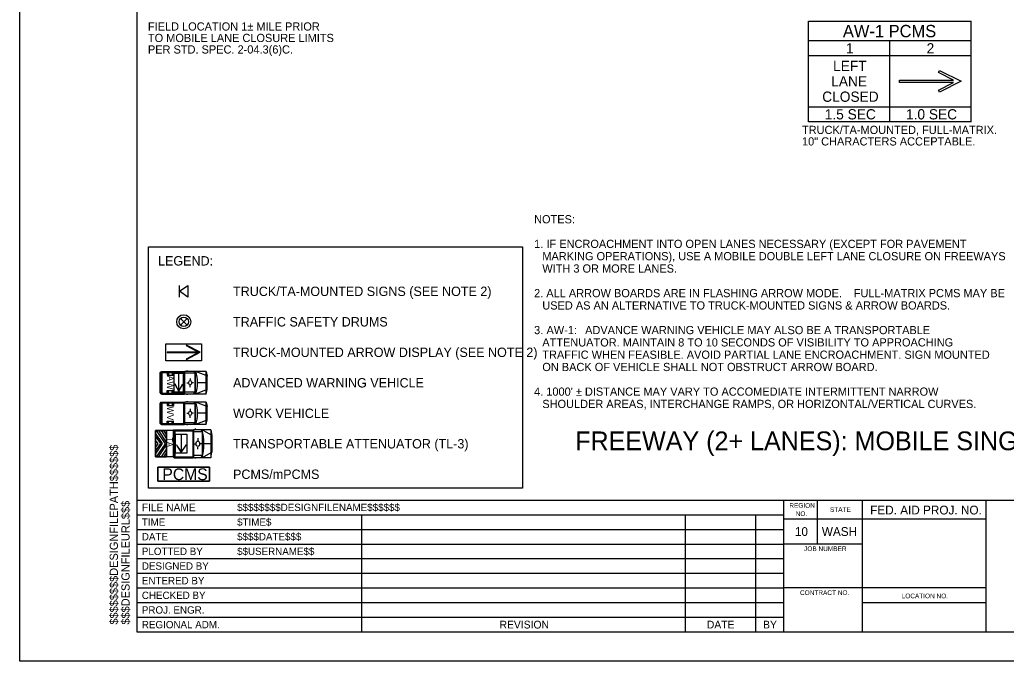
# Model space of a CAD drawing. Extents: x 0 to 17, y 0 to 11.
# Drawn here: x 0 to 8.42, y 0 to 5.47 of the extents above; entities that cross this region are included whole.
import ezdxf

# ---------------------------------------------------------------- set-up
doc = ezdxf.new("R2010")
doc.units = 0
for name, color, linetype in [('SH_GI_PlotLimits', 7, 'Continuous'), ('SH_GI_SheetBorder1', 7, 'Continuous'), ('SH_GI_SheetBorder2', 7, 'Continuous'), ('SH_GI_SheetBorder3', 7, 'Continuous'), ('SH_GI_SheetTextInCells', 7, 'Continuous'), ('SH_GI_TitleBlockText', 7, 'Continuous'), ('TR_WZ_PCMS', 7, 'Continuous'), ('TR_WZ_PortableChangeMessageSign', 7, 'Continuous'), ('TR_WZ_PortableSignMountBlk-Org', 7, 'Continuous'), ('TR_WZ_ProtectiveVehicle', 7, 'Continuous'), ('TR_WZ_TrafficSafetyDrum', 7, 'Continuous'), ('TR_WZ_TransportableAttenuator', 7, 'Continuous'), ('TR_WZ_WorkZoneTextCurrent', 7, 'Continuous')]:
    doc.layers.add(name, color=color, linetype=linetype)

msp = doc.modelspace()

# ---------------------------------------------------------------- linework, layer by layer
at = {"layer": 'SH_GI_PlotLimits'}
msp.add_lwpolyline([(0, 11), (17, 11), (17, 0), (0, 0)], close=True, dxfattribs=at)
at = {"layer": 'SH_GI_SheetBorder1'}
for p, q in [((8.245, 1.2125), (6.52, 1.2125)), ((1, 1.125), (2.92, 1.125)), ((2.92, 1.125), (6.52, 1.125)), ((1, 1), (2.92, 1)), ((2.92, 1), (6.52, 1)), ((1, 0.875), (2.92, 0.875)), ((2.92, 0.875), (6.52, 0.875)), ((1, 0.75), (2.92, 0.75)), ((2.92, 0.75), (6.52, 0.75)), ((1, 0.625), (2.92, 0.625)), ((2.92, 0.625), (6.52, 0.625)), ((1, 0.5), (2.92, 0.5)), ((2.92, 0.5), (6.52, 0.5)), ((7.1913, 0.5), (8.245, 0.5)), ((1, 0.375), (2.92, 0.375))]:
    msp.add_line(p, q, dxfattribs=at)
at = {"layer": 'SH_GI_SheetBorder2'}
for p, q in [((6.8073, 1), (6.8073, 1.375)), ((7.1913, 1), (6.52, 1)), ((8.245, 0.625), (6.52, 0.625)), ((2.92, 0.375), (6.52, 0.375))]:
    msp.add_line(p, q, dxfattribs=at)
at = {"layer": 'SH_GI_SheetBorder3'}
for p, q in [((1, 10.75), (1, 0.25)), ((1, 1.375), (16.75, 1.375)), ((6.52, 0.25), (6.52, 1.375)), ((7.1913, 0.25), (7.1913, 1.375)), ((8.245, 0.25), (8.245, 1.375)), ((1, 1.25), (6.52, 1.25)), ((2.92, 0.25), (2.92, 1.25)), ((5.68, 0.25), (5.68, 1.25)), ((6.28, 0.25), (6.28, 1.25)), ((1, 0.25), (16.75, 0.25))]:
    msp.add_line(p, q, dxfattribs=at)
at = {"layer": 'TR_WZ_PCMS'}
for points in [[(1.6191, 1.655), (1.6191, 1.535), (1.1791, 1.535), (1.1791, 1.655), (1.6191, 1.655)], [(1.1791, 1.655), (1.1791, 1.535), (1.6191, 1.535), (1.6191, 1.655), (1.1791, 1.655)]]:
    msp.add_lwpolyline(points, dxfattribs=at)
at = {"layer": 'TR_WZ_PortableChangeMessageSign'}
for p, q in [((6.7302, 5.4586), (8.1162, 5.4586)), ((6.7302, 4.6018), (6.7302, 5.4586)), ((8.1162, 4.6018), (8.1162, 5.4586)), ((8.1162, 5.2906), (6.7302, 5.2906)), ((7.4232, 4.6018), (7.4232, 5.2906)), ((7.4232, 5.1646), (6.7302, 5.1646)), ((8.1162, 5.1646), (7.4232, 5.1646)), ((7.8483, 5.0395), (8.0322, 4.9462)), ((7.5072, 4.9357), (7.5072, 4.9567)), ((7.5072, 4.9567), (7.9671, 4.9567)), ((7.9671, 4.9357), (7.5072, 4.9357)), ((6.7302, 4.7278), (7.4232, 4.7278)), ((7.4232, 4.7278), (8.1162, 4.7278)), ((8.1162, 4.6018), (6.7302, 4.6018))]:
    msp.add_line(p, q, dxfattribs=at)
for points in [[(7.9671, 4.9567), (7.8389, 5.0208), (7.8436, 5.0302), (7.8483, 5.0395)], [(8.0322, 4.9462), (7.8483, 4.8528), (7.8436, 4.8622), (7.8389, 4.8715), (7.9671, 4.9357)]]:
    msp.add_lwpolyline(points, dxfattribs=at)
at = {"layer": 'TR_WZ_PortableSignMountBlk-Org'}
msp.add_line((1.3631, 3.105), (1.3631, 3.205), dxfattribs=at)
msp.add_lwpolyline([(1.3631, 3.155), (1.435, 3.205), (1.435, 3.105)], close=True, dxfattribs=at)
at = {"layer": 'TR_WZ_ProtectiveVehicle'}
for p, q in [((1.1993, 2.288), (1.1993, 2.462)), ((1.2035, 2.4678), (1.2078, 2.4678)), ((1.2078, 2.2822), (1.2078, 2.4678)), ((1.2085, 2.471), (1.406, 2.471)), ((1.2085, 2.279), (1.2085, 2.471)), ((1.2141, 2.2867), (1.2141, 2.4633)), ((1.2141, 2.4633), (1.4004, 2.4633)), ((1.2586, 2.4633), (1.2586, 2.4413)), ((1.2586, 2.4413), (1.3114, 2.4413)), ((1.2692, 2.4633), (1.2692, 2.4413)), ((1.3018, 2.4633), (1.3018, 2.4413)), ((1.3114, 2.4633), (1.3114, 2.4413)), ((1.4004, 2.2867), (1.4004, 2.4633)), ((1.406, 2.279), (1.406, 2.471)), ((1.4086, 2.279), (1.4086, 2.471)), ((1.59, 2.471), (1.4086, 2.471)), ((1.4976, 2.4561), (1.4086, 2.4561)), ((1.4334, 2.4737), (1.4225, 2.4737)), ((1.4881, 2.4561), (1.4976, 2.471)), ((1.4976, 2.279), (1.4976, 2.471)), ((1.4993, 2.279), (1.4993, 2.471)), ((1.59, 2.4358), (1.4993, 2.471)), ((1.59, 2.279), (1.59, 2.471)), ((1.59, 2.471), (1.5989, 2.4322)), ((1.1993, 2.3885), (1.2078, 2.3849)), ((1.1993, 2.3615), (1.2078, 2.3651)), ((1.2016, 2.375), (1.2055, 2.375)), ((1.2035, 2.3723), (1.2035, 2.3777)), ((1.4245, 2.3757), (1.4388, 2.3754)), ((1.4406, 2.3753), (1.4406, 2.3753)), ((1.4535, 2.4119), (1.4537, 2.3975)), ((1.4831, 2.3749), (1.471, 2.3749)), ((1.59, 2.375), (1.5171, 2.375)), ((1.5989, 2.3178), (1.5989, 2.4322)), ((1.2035, 2.2822), (1.2078, 2.2822)), ((1.2085, 2.279), (1.406, 2.279)), ((1.2141, 2.2867), (1.4004, 2.2867)), ((1.2586, 2.3087), (1.3114, 2.3087)), ((1.2586, 2.2867), (1.2586, 2.3087)), ((1.2692, 2.2867), (1.2692, 2.3087)), ((1.3018, 2.2867), (1.3018, 2.3087)), ((1.3114, 2.2867), (1.3114, 2.3087)), ((1.4976, 2.2939), (1.4086, 2.2939)), ((1.59, 2.279), (1.4086, 2.279)), ((1.4334, 2.2763), (1.4225, 2.2763)), ((1.4541, 2.3369), (1.4541, 2.3525)), ((1.4976, 2.279), (1.4861, 2.2939)), ((1.59, 2.3142), (1.4993, 2.279)), ((1.59, 2.279), (1.5989, 2.3178)), ((1.1993, 2.028), (1.1993, 2.202)), ((1.2035, 2.2078), (1.2078, 2.2078)), ((1.2078, 2.0222), (1.2078, 2.2078)), ((1.2085, 2.211), (1.406, 2.211)), ((1.2085, 2.019), (1.2085, 2.211)), ((1.2141, 2.0267), (1.2141, 2.2033)), ((1.2141, 2.2033), (1.4004, 2.2033)), ((1.2586, 2.2033), (1.2586, 2.1813)), ((1.2692, 2.2033), (1.2692, 2.1813)), ((1.3018, 2.2033), (1.3018, 2.1813)), ((1.3114, 2.2033), (1.3114, 2.1813)), ((1.4004, 2.0267), (1.4004, 2.2033)), ((1.406, 2.019), (1.406, 2.211)), ((1.4086, 2.019), (1.4086, 2.211)), ((1.59, 2.211), (1.4086, 2.211)), ((1.4976, 2.1961), (1.4086, 2.1961)), ((1.4334, 2.2137), (1.4225, 2.2137)), ((1.4881, 2.1961), (1.4976, 2.211)), ((1.4976, 2.019), (1.4976, 2.211)), ((1.4993, 2.019), (1.4993, 2.211)), ((1.59, 2.1758), (1.4993, 2.211)), ((1.59, 2.019), (1.59, 2.211)), ((1.59, 2.211), (1.5989, 2.1722)), ((1.1993, 2.1285), (1.2078, 2.1249)), ((1.1993, 2.1015), (1.2078, 2.1051)), ((1.2016, 2.115), (1.2055, 2.115)), ((1.2035, 2.1123), (1.2035, 2.1177)), ((1.2586, 2.1813), (1.3114, 2.1813)), ((1.4245, 2.1157), (1.4388, 2.1154)), ((1.4406, 2.1153), (1.4406, 2.1153)), ((1.4535, 2.1519), (1.4537, 2.1375)), ((1.4831, 2.1149), (1.471, 2.1149)), ((1.59, 2.115), (1.5171, 2.115)), ((1.5989, 2.0578), (1.5989, 2.1722)), ((1.2035, 2.0222), (1.2078, 2.0222)), ((1.2141, 2.0267), (1.4004, 2.0267)), ((1.2586, 2.0487), (1.3114, 2.0487)), ((1.2586, 2.0267), (1.2586, 2.0487)), ((1.2692, 2.0267), (1.2692, 2.0487)), ((1.3018, 2.0267), (1.3018, 2.0487)), ((1.3114, 2.0267), (1.3114, 2.0487)), ((1.4976, 2.0339), (1.4086, 2.0339)), ((1.4541, 2.0769), (1.4541, 2.0925)), ((1.4976, 2.019), (1.4861, 2.0339)), ((1.59, 2.0542), (1.4993, 2.019)), ((1.59, 2.019), (1.5989, 2.0578)), ((1.2085, 2.019), (1.406, 2.019)), ((1.59, 2.019), (1.4086, 2.019)), ((1.4334, 2.0163), (1.4225, 2.0163))]:
    msp.add_line(p, q, dxfattribs=at)
for centre, major_axis, start_param, end_param in [((1.2035, 2.462), (0, 0.00586), 0, 1.570796), ((1.3697, 2.375), (0, 0.2015), 4.215667, 5.208926), ((1.2035, 2.288), (0, -0.00586), 4.712389, 6.283185), ((1.2035, 2.202), (0, 0.00586), 0, 1.570796), ((1.3697, 2.115), (0, 0.2015), 4.215667, 5.208926), ((1.2035, 2.028), (0, -0.00586), 4.712389, 6.283185)]:
    msp.add_ellipse(centre, major_axis=major_axis, ratio=0.73155, start_param=start_param, end_param=end_param, dxfattribs=at)
for centre, major_axis in [((1.2035, 2.375), (0, -0.0027)), ((1.4541, 2.375), (0, -0.0185)), ((1.2035, 2.115), (0, -0.0027)), ((1.4541, 2.115), (0, -0.0185))]:
    msp.add_ellipse(centre, major_axis=major_axis, ratio=0.73155, dxfattribs=at)
at = {"layer": 'TR_WZ_TrafficSafetyDrum'}
for p, q in [((1.3708, 2.9233), (1.4273, 2.8667)), ((1.4273, 2.9233), (1.3708, 2.8667))]:
    msp.add_line(p, q, dxfattribs=at)
for radius in [0.06, 0.06, 0.04]:
    msp.add_circle((1.3991, 2.895), radius, dxfattribs=at)
at = {"layer": 'TR_WZ_TransportableAttenuator'}
for p, q in [((1.1591, 1.9173), (1.1591, 1.9465)), ((1.2192, 1.8559), (1.1591, 1.9465)), ((1.1591, 1.9465), (1.1591, 1.9173)), ((1.1653, 1.9679), (1.1857, 1.9679)), ((1.1653, 1.9679), (1.2401, 1.8552)), ((1.1857, 1.9679), (1.1653, 1.9679)), ((1.2534, 1.8652), (1.1857, 1.9679)), ((1.2078, 1.9679), (1.2281, 1.9679)), ((1.2281, 1.9679), (1.2078, 1.9679)), ((1.2078, 1.9679), (1.2534, 1.8984)), ((1.2534, 1.9298), (1.2281, 1.9679)), ((1.3178, 1.9679), (1.2534, 1.9679)), ((1.2534, 1.7426), (1.2534, 1.9679)), ((1.3102, 1.9638), (1.3102, 1.7463)), ((1.3137, 1.9711), (1.3173, 1.9711)), ((1.3173, 1.9711), (1.3173, 1.739)), ((1.3178, 1.975), (1.4803, 1.975)), ((1.3178, 1.975), (1.3178, 1.735)), ((1.3178, 1.9675), (1.3178, 1.7426)), ((1.3224, 1.9655), (1.3224, 1.7446)), ((1.3224, 1.9655), (1.4757, 1.9655)), ((1.4757, 1.9655), (1.4757, 1.7446)), ((1.4803, 1.975), (1.4803, 1.735)), ((1.4825, 1.975), (1.4825, 1.735)), ((1.6317, 1.975), (1.4825, 1.975)), ((1.5558, 1.9564), (1.4825, 1.9564)), ((1.5028, 1.9784), (1.4939, 1.9784)), ((1.5558, 1.975), (1.5463, 1.9564)), ((1.5558, 1.975), (1.5558, 1.735)), ((1.5571, 1.975), (1.5571, 1.735)), ((1.6317, 1.9311), (1.5571, 1.975)), ((1.6317, 1.975), (1.6317, 1.735)), ((1.6317, 1.975), (1.6391, 1.9266)), ((1.1591, 1.9173), (1.1999, 1.8562)), ((1.1591, 1.824), (1.1591, 1.8864)), ((1.1799, 1.8554), (1.1591, 1.8864)), ((1.1591, 1.8864), (1.1591, 1.824)), ((1.1999, 1.8562), (1.1591, 1.7948)), ((1.1591, 1.7654), (1.2192, 1.8559)), ((1.1591, 1.824), (1.1799, 1.8554)), ((1.2401, 1.8552), (1.1652, 1.7425)), ((1.2534, 1.9298), (1.2534, 1.8984)), ((1.2534, 1.8984), (1.2534, 1.9298)), ((1.2534, 1.8652), (1.2534, 1.8451)), ((1.2534, 1.8451), (1.2534, 1.8652)), ((1.3102, 1.8719), (1.3173, 1.8674)), ((1.3121, 1.855), (1.3154, 1.855)), ((1.3137, 1.8584), (1.3137, 1.8516)), ((1.4882, 1.8552), (1.5015, 1.8551)), ((1.5051, 1.8546), (1.5051, 1.8546)), ((1.52, 1.9026), (1.5199, 1.8832)), ((1.5517, 1.8552), (1.5384, 1.8551)), ((1.6317, 1.855), (1.5718, 1.855)), ((1.6391, 1.9266), (1.6391, 1.7835)), ((1.1591, 1.7654), (1.1591, 1.7948)), ((1.1591, 1.7948), (1.1591, 1.7654)), ((1.1853, 1.7425), (1.2534, 1.8451)), ((1.2534, 1.8119), (1.2073, 1.7425)), ((1.2288, 1.7425), (1.2534, 1.7788)), ((1.2534, 1.8119), (1.2534, 1.7788)), ((1.2534, 1.7788), (1.2534, 1.8119)), ((1.3102, 1.8381), (1.3173, 1.8426)), ((1.52, 1.8075), (1.5199, 1.8269)), ((1.6317, 1.779), (1.5571, 1.735)), ((1.6317, 1.735), (1.6391, 1.7835)), ((1.1853, 1.7425), (1.1652, 1.7425)), ((1.1652, 1.7425), (1.1853, 1.7425)), ((1.2288, 1.7425), (1.2073, 1.7425)), ((1.2073, 1.7425), (1.2288, 1.7425)), ((1.3178, 1.7426), (1.2534, 1.7426)), ((1.3137, 1.739), (1.3173, 1.739)), ((1.3178, 1.735), (1.4803, 1.735)), ((1.3224, 1.7446), (1.4757, 1.7446)), ((1.5558, 1.7536), (1.4825, 1.7536)), ((1.6317, 1.735), (1.4825, 1.735)), ((1.5028, 1.7317), (1.4939, 1.7317)), ((1.5479, 1.7536), (1.5558, 1.735))]:
    msp.add_line(p, q, dxfattribs=at)
for points in [[(1.2464, 2.563), (1.2464, 2.707), (1.5517, 2.707), (1.5517, 2.563)], [(1.5395, 2.635), (1.4232, 2.697), (1.4199, 2.693), (1.5241, 2.6374)], [(1.2587, 2.6326), (1.5241, 2.6326), (1.5241, 2.6374), (1.2587, 2.6374)], [(1.4232, 2.573), (1.5395, 2.635), (1.5241, 2.6326), (1.4199, 2.577)], [(1.5395, 2.635), (1.5241, 2.6374), (1.5241, 2.6326)], [(1.3183, 2.4564), (1.3951, 2.4564), (1.3951, 2.2936), (1.3183, 2.2936)], [(1.3554, 2.4499), (1.3554, 2.3083), (1.358, 2.3083), (1.358, 2.4499)], [(1.3236, 2.3621), (1.3567, 2.3001), (1.3554, 2.3083), (1.3257, 2.3639)], [(1.3567, 2.3001), (1.3897, 2.3621), (1.3876, 2.3639), (1.358, 2.3083)], [(1.3567, 2.3001), (1.358, 2.3083), (1.3554, 2.3083)], [(1.2534, 1.7425), (1.1591, 1.7425), (1.1591, 1.9679), (1.2534, 1.9679)], [(1.3304, 1.9365), (1.4264, 1.9365), (1.4264, 1.7736), (1.3304, 1.7736)], [(1.3768, 1.9299), (1.3768, 1.7883), (1.38, 1.7883), (1.38, 1.9299)], [(1.3371, 1.8422), (1.3784, 1.7802), (1.3768, 1.7883), (1.3397, 1.8439)], [(1.3784, 1.7802), (1.38, 1.7883), (1.3768, 1.7883)], [(1.3784, 1.7802), (1.4197, 1.8422), (1.4171, 1.8439), (1.38, 1.7883)]]:
    msp.add_lwpolyline(points, close=True, dxfattribs=at)
msp.add_lwpolyline([(1.2534, 1.9679), (1.1591, 1.9679), (1.1591, 1.7425), (1.2534, 1.7426)], dxfattribs=at)
for centre, major_axis, start_param, end_param in [((1.3137, 1.9638), (0, 0.00732), 6.283185, 7.853982), ((1.4505, 1.855), (0, 0.2519), 4.215852, 5.209111), ((1.3137, 1.7463), (0, -0.00732), 4.712389, 6.283185)]:
    msp.add_ellipse(centre, major_axis=major_axis, ratio=0.481608, start_param=start_param, end_param=end_param, dxfattribs=at)
for centre, major_axis, ratio in [((1.3137, 1.855), (0, -0.00338), 0.481608), ((1.5199, 1.855), (0, -0.0231), 0.642144), ((1.5199, 1.855), (0, 0.0231), 0.642144)]:
    msp.add_ellipse(centre, major_axis=major_axis, ratio=ratio, dxfattribs=at)
at = {"layer": 'TR_WZ_WorkZoneTextCurrent'}
msp.add_lwpolyline([(1.1, 3.535), (4.2886, 3.535), (4.2886, 1.475), (1.1, 1.475)], close=True, dxfattribs=at)

# ---------------------------------------------------------------- texts
at = {"layer": 'SH_GI_SheetTextInCells'}
for s, height, p in [('REGION', 0.04, (6.5662, 1.3088)), ('FILE NAME', 0.065, (1.042, 1.28)), ('NO.', 0.04, (6.6206, 1.2387)), ('STATE', 0.04, (6.9129, 1.2738)), ('FED. AID PROJ. NO.', 0.075, (7.2558, 1.252)), ('TIME', 0.0625, (1.042, 1.1562)), ('10', 0.075, (6.6136, 1.0688)), ('WASH', 0.075, (6.8434, 1.0688)), ('DATE', 0.0625, (1.042, 1.0312)), ('PLOTTED BY', 0.0625, (1.042, 0.9062)), ('JOB NUMBER', 0.04, (6.6925, 0.94)), ('DESIGNED BY', 0.0625, (1.042, 0.7812)), ('ENTERED BY', 0.0625, (1.042, 0.6562)), ('CHECKED BY', 0.0625, (1.042, 0.5312)), ('CONTRACT NO.', 0.04, (6.6574, 0.565)), ('LOCATION NO.', 0.04, (7.5244, 0.537)), ('PROJ. ENGR.', 0.0625, (1.042, 0.4062)), ('REGIONAL ADM.', 0.0625, (1.042, 0.2812)), ('REVISION', 0.066, (4.0938, 0.2795)), ('DATE', 0.066, (5.8627, 0.2795)), ('BY', 0.066, (6.3424, 0.2795))]:
    msp.add_text(s, height=height, dxfattribs=at).set_placement(p)
at = {"layer": 'SH_GI_TitleBlockText'}
for s, p in [('$$$$$$$$DESIGNFILEPATH$$$$$$', (0.8377, 0.3125)), ('$$$DESIGNFILEURL$$$', (0.9375, 0.3125))]:
    msp.add_text(s, height=0.07, rotation=90, dxfattribs=at).set_placement(p)
for s, p in [('$$$$$$$$DESIGNFILENAME$$$$$$', (1.8545, 1.2812)), ('$TIME$', (1.8545, 1.1562)), ('$$$$DATE$$$', (1.8545, 1.0312)), ('$$USERNAME$$', (1.8545, 0.9062))]:
    msp.add_text(s, height=0.0625, dxfattribs=at).set_placement(p)
at = {"layer": 'TR_WZ_PCMS'}
msp.add_text('PCMS', height=0.1, rotation=360, dxfattribs=at).set_placement((1.2173, 1.545))
at = {"layer": 'TR_WZ_PortableChangeMessageSign'}
for s, height, p in [('FIELD LOCATION 1± MILE PRIOR ', 0.07, (1.0938, 5.3789)), ('AW-1 PCMS', 0.105, (7.0234, 5.3221)), ('TO MOBILE LANE CLOSURE LIMITS ', 0.07, (1.0938, 5.2809)), ('PER STD. SPEC. 2-04.3(6)C.', 0.07, (1.0938, 5.1829)), ('1', 0.0875, (7.0494, 5.1838)), ('2', 0.0875, (7.7373, 5.1838)), ('LEFT', 0.0875, (6.9395, 5.0337)), ('LANE', 0.0875, (6.9235, 4.9024)), ('CLOSED', 0.0875, (6.847, 4.7712)), ('1.5 SEC', 0.0875, (6.8685, 4.621)), ('1.0 SEC', 0.0875, (7.5615, 4.621)), ('TRUCK/TA-MOUNTED, FULL-MATRIX.', 0.07, (6.6743, 4.4968)), ('10" CHARACTERS ACCEPTABLE.', 0.07, (6.6743, 4.3988))]:
    msp.add_text(s, height=height, rotation=360, dxfattribs=at).set_placement(p)
at = {"layer": 'TR_WZ_ProtectiveVehicle'}
for s, p in [('AW', (1.257, 2.4371)), ('WV', (1.257, 2.1743))]:
    msp.add_text(s, height=0.056, rotation=270, dxfattribs=at).set_placement(p)
at = {"layer": 'TR_WZ_TransportableAttenuator'}
msp.add_text('TA', height=0.048, rotation=270, dxfattribs=at).set_placement((1.2572, 1.9097))
at = {"layer": 'TR_WZ_WorkZoneTextCurrent'}
for s, height, p in [('NOTES:', 0.07, (4.3886, 3.7347)), ('1. ', 0.07, (4.3886, 3.5247)), ('IF ENCROACHMENT INTO OPEN LANES NECESSARY (EXCEPT FOR PAVEMENT ', 0.07, (4.4943, 3.5247)), ('LEGEND:', 0.08, (1.18, 3.375)), ('MARKING OPERATIONS), USE A MOBILE DOUBLE LEFT LANE CLOSURE ON FREEWAYS ', 0.07, (4.4586, 3.4197)), ('WITH 3 OR MORE LANES.', 0.07, (4.4586, 3.3147)), ('TRUCK/TA-MOUNTED SIGNS (SEE NOTE 2)', 0.08, (1.82, 3.115)), ('2. ALL ARROW BOARDS ARE IN FLASHING ARROW MODE. ', 0.07, (4.3886, 3.1047)), ('FULL-MATRIX PCMS MAY BE ', 0.07, (7.1158, 3.1047)), ('USED AS AN ALTERNATIVE TO TRUCK-MOUNTED SIGNS & ARROW BOARDS.', 0.07, (4.4586, 2.9997)), ('TRAFFIC SAFETY DRUMS', 0.08, (1.82, 2.855)), ('3. ', 0.07, (4.3886, 2.7897)), ('AW-1:', 0.07, (4.4943, 2.7897)), (' ADVANCE WARNING VEHICLE MAY ALSO BE A TRANSPORTABLE ', 0.07, (4.7978, 2.7897)), ('ATTENUATOR. MAINTAIN 8 TO 10 SECONDS OF VISIBILITY TO APPROACHING ', 0.07, (4.4586, 2.6847)), ('TRUCK-MOUNTED ARROW DISPLAY (SEE NOTE 2)', 0.08, (1.82, 2.595)), ('TRAFFIC WHEN FEASIBLE. AVOID PARTIAL LANE ENCROACHMENT. SIGN MOUNTED ', 0.07, (4.4586, 2.5797)), ('ON BACK OF VEHICLE SHALL NOT OBSTRUCT ARROW BOARD.', 0.07, (4.4586, 2.4747)), ('ADVANCED WARNING VEHICLE', 0.08, (1.82, 2.335)), ("4. 1000' ± DISTANCE MAY VARY TO ACCOMEDIATE INTERMITTENT NARROW ", 0.07, (4.3886, 2.2647)), ('SHOULDER AREAS, INTERCHANGE RAMPS, OR HORIZONTAL/VERTICAL CURVES. ', 0.07, (4.4586, 2.1597)), ('WORK VEHICLE', 0.08, (1.82, 2.075)), ('FREEWAY (2+ LANES): MOBILE SINGLE LEFT LANE CLOSURE, EXCLUDING PAVEMENT MARKING OPERATIONS', 0.16, (4.7391, 1.7997)), ('TRANSPORTABLE ATTENUATOR (TL-3)', 0.08, (1.82, 1.815)), ('PCMS/mPCMS', 0.08, (1.82, 1.555))]:
    msp.add_text(s, height=height, rotation=360, dxfattribs=at).set_placement(p)

doc.saveas('drawing.dxf')
